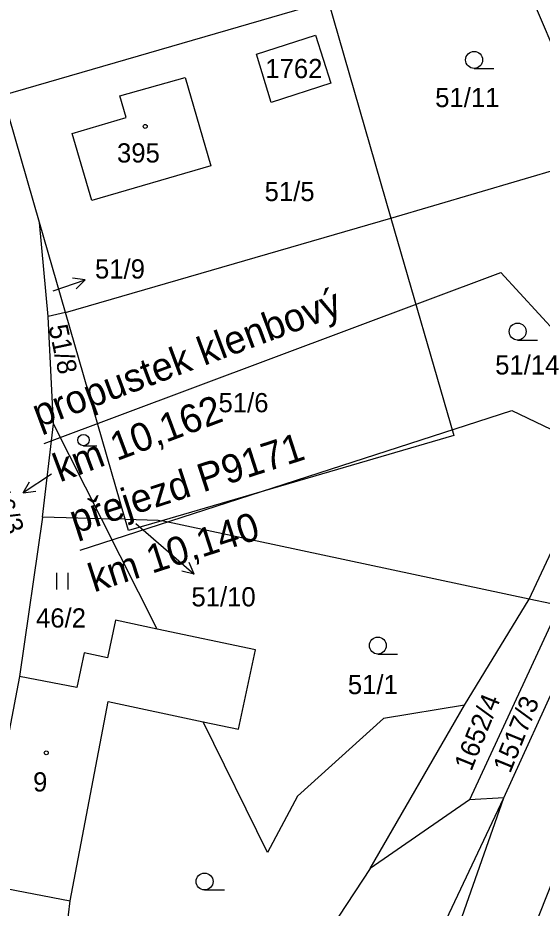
# Model space of a CAD drawing. Extents: x -553916 to -552953, y -1067469 to -1066637.
# Drawn here: x -553578.9 to -553532.5, y -1067025.6 to -1066946.9 of the extents above; entities that cross this region are included whole.
import ezdxf

# ---------------------------------------------------------------- set-up
doc = ezdxf.new("R2010")
doc.units = 0
for name, color, linetype in [('Hranice parcel', 7, 'Continuous'), ('Parcelní čísla', 7, 'Continuous'), ('Pop  PČ popisy', 7, 'Continuous'), ('Propustek', 7, 'Continuous'), ('Přejezd - štěrkové lože', 7, 'Continuous'), ('Vrstva 1', 7, 'Continuous'), ('Značky budov', 7, 'Continuous'), ('Značky kultur', 7, 'Continuous')]:
    doc.layers.add(name, color=color, linetype=linetype)

msp = doc.modelspace()

# ---------------------------------------------------------------- linework, layer by layer
at = {"layer": 'Hranice parcel'}
for p, q in [((-553580.22, -1066953.72), (-553551.41, -1066945.38)), ((-553551.41, -1066945.38), (-553545.85, -1066964.59)), ((-553576.96, -1066964.99), (-553580.22, -1066953.72)), ((-553545.85, -1066964.59), (-553527.43, -1066959.15)), ((-553576.19, -1066973.29), (-553576.96, -1066964.99)), ((-553574.66, -1066972.93), (-553576.96, -1066964.99)), ((-553574.66, -1066972.93), (-553545.85, -1066964.59)), ((-553545.85, -1066964.59), (-553540.29, -1066983.8)), ((-553574.66, -1066972.93), (-553576.19, -1066973.29)), ((-553575.72, -1066982.77), (-553576.19, -1066973.29)), ((-553569.37, -1066991.22), (-553574.66, -1066972.93)), ((-553576.7, -1066991.04), (-553575.72, -1066982.77)), ((-553571.48, -1066991.17), (-553575.72, -1066982.77)), ((-553540.29, -1066983.8), (-553566.13, -1066991.36)), ((-553576.7, -1066991.04), (-553578.74, -1067005.13)), ((-553571.48, -1066991.17), (-553576.7, -1066991.04)), ((-553566.55, -1067000.93), (-553571.48, -1066991.17)), ((-553569.37, -1066991.22), (-553571.48, -1066991.17)), ((-553533.63, -1066998.28), (-553566.13, -1066991.36)), ((-553539.34, -1067007.65), (-553533.63, -1066998.28)), ((-553530.98, -1066998.99), (-553538.9, -1067016.05)), ((-553535.85, -1067015.85), (-553528.66, -1067000.03)), ((-553578.74, -1067005.13), (-553582.25, -1067023.44)), ((-553547.68, -1067022.12), (-553539.34, -1067007.65)), ((-553555.44, -1067071.33), (-553535.85, -1067015.85)), ((-553538.9, -1067016.05), (-553547.68, -1067022.12)), ((-553535.85, -1067015.85), (-553538.9, -1067016.05)), ((-553582.25, -1067023.44), (-553574.24, -1067024.96)), ((-553575.44, -1067034.44), (-553574.24, -1067024.96))]:
    msp.add_line(p, q, dxfattribs=at)
for points in [[(-553556.45, -1066954.37), (-553557.77, -1066950.08), (-553552.53, -1066948.42), (-553551.19, -1066952.66), (-553556.45, -1066954.37)], [(-553574.08, -1066957.11), (-553569.3, -1066955.7), (-553569.85, -1066953.76), (-553564.08, -1066952.14), (-553561.8, -1066959.96), (-553572.32, -1066963.04), (-553574.08, -1066957.11)], [(-553533.63, -1066998.28), (-553526.12, -1066982.3), (-553521.68, -1066973.05)], [(-553569.37, -1066991.22), (-553566.45, -1066991.29), (-553566.13, -1066991.36)], [(-553566.13, -1066991.36), (-553569.08, -1066992.22), (-553569.37, -1066991.22)], [(-553515.43, -1066991.08), (-553526.38, -1067010.19), (-553539.65, -1067043.59), (-553548.33, -1067069.03)], [(-553530.98, -1066998.99), (-553531.64, -1066998.7), (-553533.63, -1066998.28)], [(-553566.55, -1067000.93), (-553570.25, -1067000.14), (-553570.96, -1067003.47), (-553573.01, -1067003.03), (-553573.66, -1067006.09), (-553578.74, -1067005.13)], [(-553562.48, -1067009.13), (-553559.34, -1067009.8), (-553557.85, -1067002.78), (-553566.55, -1067000.93)], [(-553574.24, -1067024.96), (-553570.9, -1067007.35), (-553562.48, -1067009.13)], [(-553539.34, -1067007.65), (-553546.5, -1067008.84), (-553554.13, -1067015.7), (-553556.77, -1067020.68), (-553562.48, -1067009.13)], [(-553547.23, -1067042.51), (-553544.77, -1067034.69), (-553535.85, -1067015.85)], [(-553547.68, -1067022.12), (-553553.91, -1067031.58), (-553557.59, -1067038.38)]]:
    msp.add_lwpolyline(points, dxfattribs=at)
at = {"layer": 'Pop  PČ popisy'}
for p, q in [((-553575.77, -1066971.03), (-553572.933, -1066970.053)), ((-553572.933, -1066970.053), (-553574.042, -1066969.906)), ((-553572.933, -1066970.053), (-553573.716, -1066970.852)), ((-553575.91, -1066987.23), (-553578.418, -1066988.878)), ((-553578.418, -1066988.878), (-553577.856, -1066987.91)), ((-553578.418, -1066988.878), (-553577.306, -1066988.747)), ((-553568.43, -1066991.61), (-553565.55, -1066994.11)), ((-553565.55, -1066994.11), (-553563.285, -1066996.079)), ((-553563.285, -1066996.079), (-553563.712, -1066995.044)), ((-553563.285, -1066996.079), (-553564.369, -1066995.8))]:
    msp.add_line(p, q, dxfattribs=at)
at = {"layer": 'Propustek'}
msp.add_lwpolyline([(-553576.56, -1066984.514), (-553536.119, -1066969.402), (-553529.408, -1066976.709), (-553517.537, -1066972.276)], dxfattribs=at)
at = {"layer": 'Přejezd - štěrkové lože'}
msp.add_lwpolyline([(-553573.367, -1066993.961), (-553535.151, -1066981.6), (-553526.82, -1066985.587), (-553514.291, -1066981.32)], dxfattribs=at)
at = {"layer": 'Vrstva 1'}
msp.add_line((-553527.43, -1066959.15), (-553535.26, -1066940.6), dxfattribs=at)
at = {"layer": 'Značky budov'}
for centre in [(-553567.607, -1066956.479), (-553576.367, -1067011.879)]:
    msp.add_circle(centre, 0.175, dxfattribs=at)
at = {"layer": 'Značky kultur'}
for p, q in [((-553538.493, -1066951.35), (-553536.743, -1066951.35)), ((-553534.638, -1066975.37), (-553532.888, -1066975.37)), ((-553573.07, -1066984.723), (-553571.898, -1066984.723)), ((-553575.423, -1066997.446), (-553575.423, -1066995.946)), ((-553574.422, -1066997.446), (-553574.422, -1066995.946)), ((-553547.013, -1067003.14), (-553545.263, -1067003.14)), ((-553562.353, -1067024.01), (-553560.603, -1067024.01))]:
    msp.add_line(p, q, dxfattribs=at)
for centre, radius in [((-553538.493, -1066950.6), 0.75), ((-553534.638, -1066974.62), 0.75), ((-553573.07, -1066984.22), 0.502), ((-553547.013, -1067002.39), 0.75), ((-553562.353, -1067023.26), 0.75)]:
    msp.add_circle(centre, radius, dxfattribs=at)

# ---------------------------------------------------------------- texts
at = {"layer": 'Parcelní čísla'}
for s, p in [('1762', (-553556.976, -1066952.208)), ('51/11', (-553541.938, -1066954.769)), ('395', (-553570.105, -1066959.67)), ('51/5', (-553557.039, -1066963.08)), ('51/9', (-553572.055, -1066969.934)), ('51/14', (-553536.628, -1066978.42)), ('51/6', (-553561.119, -1066981.759)), ('51/10', (-553563.518, -1066998.928)), ('46/2', (-553577.277, -1067000.8)), ('51/1', (-553549.669, -1067006.69)), ('9', (-553577.536, -1067015.3))]:
    msp.add_text(s, height=1.7, dxfattribs=at).set_placement(p)
for s, rotation, p in [('51/8', 282, (-553576.179, -1066974.183)), ('46/3', 291, (-553581.434, -1066988.581)), ('1652/4', 68, (-553538.741, -1067013.58)), ('1517/3', 68, (-553535.299, -1067013.759))]:
    msp.add_text(s, height=1.7, rotation=rotation, dxfattribs=at).set_placement(p)
at = {"layer": 'Propustek'}
for s, p in [('propustek klenbový', (-553577.034, -1066983.13)), ('km 10,162', (-553575.169, -1066987.971))]:
    msp.add_text(s, height=2.5, rotation=20.48994, dxfattribs=at).set_placement(p)
at = {"layer": 'Přejezd - štěrkové lože'}
for s, p in [('přejezd P9171', (-553573.821, -1066992.515)), ('km 10,140', (-553572.143, -1066997.703))]:
    msp.add_text(s, height=2.5, rotation=17.92384, dxfattribs=at).set_placement(p)

doc.saveas('drawing.dxf')
